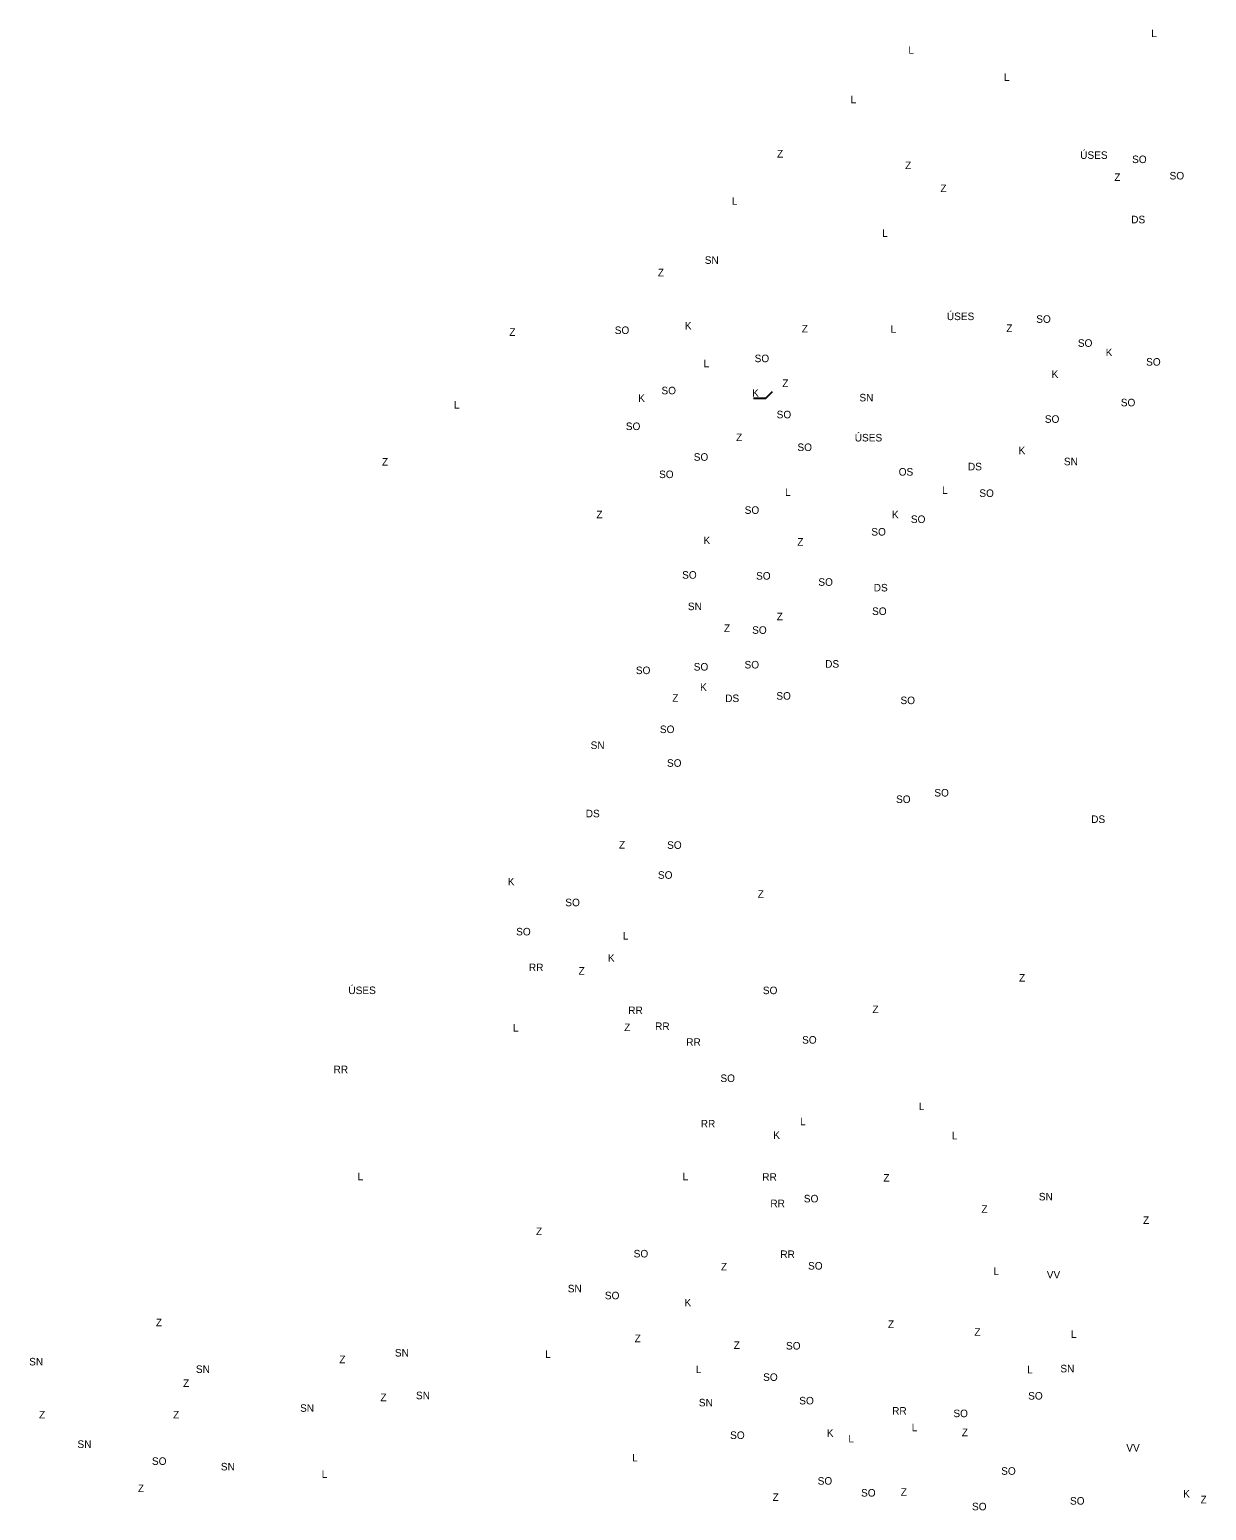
# Model space of a CAD drawing. Extents: x -445021 to -431236, y -1134464 to -1129615.
# Drawn here: x -443696 to -442135, y -1132159 to -1130195 of the extents above; entities that cross this region are included whole.
import ezdxf

# ---------------------------------------------------------------- set-up
doc = ezdxf.new("R2010")
doc.units = 0
doc.layers.add('Vrstva 84', color=7, linetype='Continuous')

msp = doc.modelspace()

# ---------------------------------------------------------------- linework, layer by layer
at = {"layer": 'Vrstva 84'}
msp.add_lwpolyline([(-442736, -1130683.7), (-442719.4, -1130683.7), (-442710.7, -1130675.1)], dxfattribs=at)

# ---------------------------------------------------------------- texts
for s, p in [('L', (-442208, -1130205.1)), ('L', (-442530.3, -1130227.2)), ('L', (-442403.5, -1130263.1)), ('L', (-442606.9, -1130292.7)), ('ÚSES', (-442302.4, -1130366.5)), ('Z', (-442704.6, -1130364.7)), ('Z', (-442534.6, -1130380)), ('SO', (-442233.5, -1130372.1)), ('Z', (-442257.1, -1130395.8)), ('SO', (-442183.8, -1130393.8)), ('Z', (-442487.8, -1130410.5)), ('L', (-442764.5, -1130427.3)), ('DS', (-442234.7, -1130451.9)), ('L', (-442565.1, -1130469.9)), ('SN', (-442800.5, -1130505.7)), ('Z', (-442862.7, -1130522.3)), ('ÚSES', (-442479.3, -1130580.3)), ('SO', (-442919.9, -1130598.7)), ('K', (-442826.9, -1130592.8)), ('Z', (-442671.7, -1130596.6)), ('L', (-442553.9, -1130597.1)), ('Z', (-442400.4, -1130596.1)), ('SO', (-442360.7, -1130583.9)), ('Z', (-443059.8, -1130601.2)), ('SO', (-442305.5, -1130615.7)), ('SO', (-442734.3, -1130636.1)), ('K', (-442268.5, -1130628.1)), ('L', (-442802, -1130642.8)), ('K', (-442340.3, -1130656.9)), ('SO', (-442214.9, -1130640.7)), ('SO', (-442857.9, -1130678.7)), ('Z', (-442697.6, -1130669)), ('L', (-443133.2, -1130697.6)), ('K', (-442888.8, -1130688.8)), ('K', (-442737.6, -1130681.9)), ('SN', (-442595.3, -1130688.1)), ('SO', (-442248.5, -1130694.6)), ('SO', (-442705.1, -1130710.5)), ('SO', (-442349.3, -1130716.5)), ('SO', (-442905.2, -1130726.1)), ('Z', (-442758.9, -1130740.7)), ('SO', (-442677.5, -1130753.9)), ('ÚSES', (-442601.5, -1130741.2)), ('Z', (-443228.8, -1130773.3)), ('SO', (-442815.1, -1130766.8)), ('K', (-442384.2, -1130758.1)), ('SN', (-442324, -1130772.8)), ('SO', (-442861.1, -1130789.8)), ('OS', (-442543.2, -1130786.5)), ('DS', (-442451.3, -1130779.5)), ('L', (-442694, -1130813.5)), ('L', (-442485.7, -1130810.8)), ('SO', (-442436.2, -1130814.8)), ('Z', (-442944.2, -1130843)), ('SO', (-442747.5, -1130837.2)), ('K', (-442552.1, -1130843.1)), ('SO', (-442527, -1130849.3)), ('SO', (-442579.5, -1130866)), ('K', (-442802.1, -1130877.3)), ('Z', (-442677.7, -1130879.4)), ('SO', (-442830.5, -1130923.2)), ('SO', (-442732.4, -1130924.4)), ('SO', (-442649.8, -1130932.6)), ('DS', (-442576.3, -1130940.1)), ('SN', (-442822.9, -1130964.9)), ('SO', (-442578.5, -1130971.3)), ('Z', (-442705, -1130978.3)), ('Z', (-442775, -1130993.9)), ('SO', (-442737.6, -1130996.3)), ('SO', (-442891.9, -1131049.7)), ('SO', (-442815.1, -1131045)), ('SO', (-442747.7, -1131042.2)), ('DS', (-442640.7, -1131041.2)), ('Z', (-442843.6, -1131086.4)), ('K', (-442806.7, -1131072)), ('DS', (-442773.4, -1131086.8)), ('SO', (-442705.5, -1131083.6)), ('SO', (-442540.8, -1131089.5)), ('SO', (-442860, -1131127.9)), ('SN', (-442951.9, -1131149)), ('SO', (-442850.6, -1131172.6)), ('SO', (-442546.7, -1131220.6)), ('SO', (-442495.9, -1131212)), ('DS', (-442958.4, -1131239.6)), ('DS', (-442287.8, -1131247.1)), ('Z', (-442914.3, -1131281)), ('SO', (-442850.4, -1131281.4)), ('SO', (-442862.6, -1131321.1)), ('K', (-443061.8, -1131329.9)), ('Z', (-442730.2, -1131346.3)), ('SO', (-442985.5, -1131357.5)), ('SO', (-443050.7, -1131396.2)), ('L', (-442909.1, -1131401.8)), ('RR', (-443033.8, -1131443.6)), ('K', (-442929, -1131431.1)), ('Z', (-442967.9, -1131448.3)), ('Z', (-442383.5, -1131457.5)), ('ÚSES', (-443273.3, -1131474)), ('SO', (-442723.4, -1131474.1)), ('RR', (-442902, -1131500.5)), ('Z', (-442578, -1131499.2)), ('RR', (-442866.4, -1131521.6)), ('L', (-443054.9, -1131523.7)), ('Z', (-442907.4, -1131523.1)), ('RR', (-442825, -1131542.6)), ('SO', (-442671.3, -1131539.7)), ('RR', (-443293, -1131578.9)), ('SO', (-442779.7, -1131590.6)), ('L', (-442516.5, -1131627.9)), ('RR', (-442805.8, -1131650.9)), ('L', (-442674.1, -1131648)), ('K', (-442709.6, -1131666)), ('L', (-442472.7, -1131666.6)), ('L', (-443261.1, -1131720.8)), ('L', (-442829.9, -1131720.8)), ('RR', (-442724.2, -1131721.5)), ('Z', (-442563.4, -1131722.6)), ('RR', (-442713.4, -1131756.6)), ('SO', (-442669, -1131750.2)), ('SN', (-442357.3, -1131747.6)), ('Z', (-442433.4, -1131764)), ('Z', (-443024.4, -1131793.6)), ('Z', (-442219, -1131778.8)), ('SO', (-442894.8, -1131823.2)), ('RR', (-442700.2, -1131824)), ('Z', (-442779, -1131840.4)), ('SO', (-442663.4, -1131839.3)), ('L', (-442417.5, -1131846.5)), ('VV', (-442346.7, -1131851)), ('SN', (-442982.2, -1131869.5)), ('SO', (-442933, -1131878.7)), ('K', (-442827.3, -1131888.1)), ('Z', (-443528.7, -1131914.5)), ('Z', (-442557.5, -1131916.8)), ('Z', (-442442.7, -1131927)), ('L', (-442314.7, -1131930)), ('SN', (-443211.6, -1131954.6)), ('Z', (-442893.5, -1131935.6)), ('Z', (-442762, -1131944.5)), ('SO', (-442692.7, -1131945.3)), ('SN', (-443696.8, -1131966.4)), ('Z', (-443285.3, -1131963.4)), ('L', (-443012.2, -1131956.5)), ('SN', (-443475.6, -1131976.3)), ('L', (-442812.3, -1131976.6)), ('SO', (-442723, -1131986.9)), ('L', (-442372.7, -1131976.9)), ('SN', (-442328.7, -1131975.6)), ('Z', (-443492.5, -1131994.9)), ('Z', (-443230.8, -1132013.8)), ('SN', (-443183.6, -1132011.2)), ('SO', (-442371.4, -1132011.7)), ('SN', (-443337.4, -1132027.9)), ('SN', (-442808.3, -1132020.7)), ('SO', (-442675.1, -1132018.1)), ('RR', (-442551.9, -1132031.6)), ('Z', (-443683.7, -1132036.7)), ('Z', (-443505.8, -1132036.7)), ('SO', (-442470.6, -1132035)), ('SO', (-442766.8, -1132063.9)), ('K', (-442638.6, -1132061.1)), ('L', (-442609.9, -1132068.5)), ('L', (-442525.9, -1132053.7)), ('Z', (-442459.4, -1132060.2)), ('SN', (-443632.7, -1132075.8)), ('VV', (-442241.2, -1132080.6)), ('SO', (-443533.9, -1132098.3)), ('SN', (-443442.5, -1132105.6)), ('L', (-442896.8, -1132093.7)), ('SO', (-442407.2, -1132111.4)), ('L', (-443308.7, -1132115.6)), ('SO', (-442650.7, -1132124.5)), ('Z', (-443552.6, -1132134.4)), ('Z', (-442710.5, -1132146.1)), ('SO', (-442593.1, -1132140.3)), ('Z', (-442540.5, -1132139.3)), ('SO', (-442315.9, -1132151)), ('K', (-442165.8, -1132141.6)), ('Z', (-442142.7, -1132149.3)), ('SO', (-442445.9, -1132158.5))]:
    msp.add_text(s, height=10, dxfattribs=at).set_placement(p)

doc.saveas('drawing.dxf')
